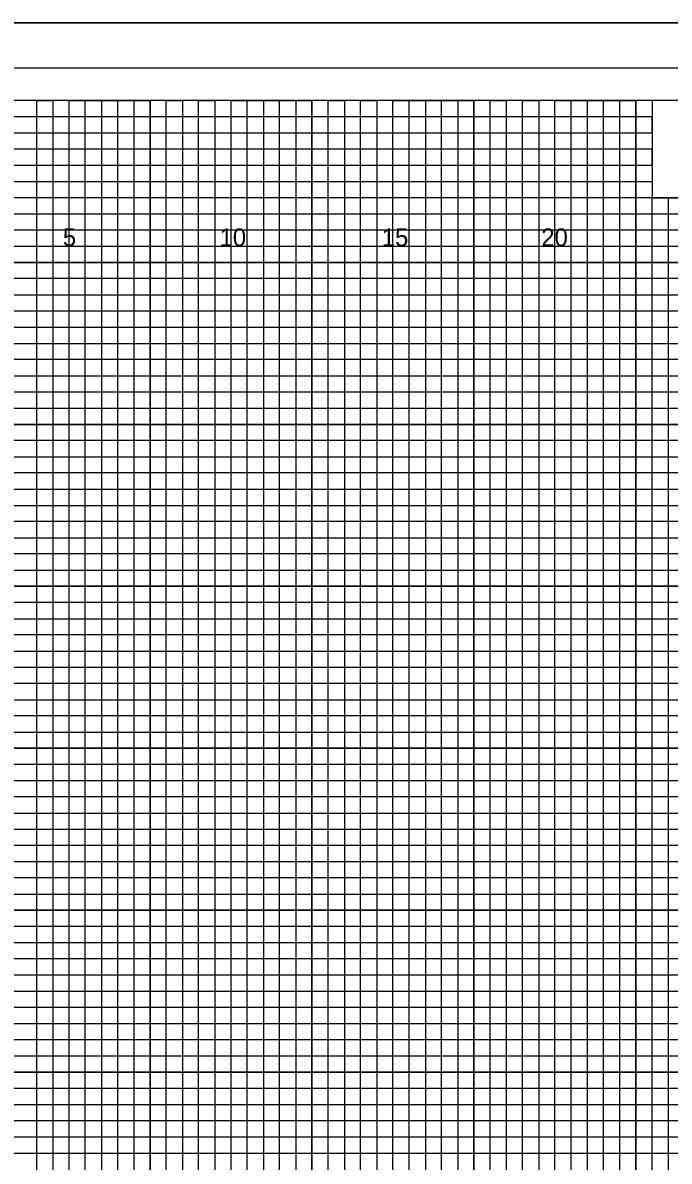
# Model space of a CAD drawing. Extents: x -4 to 103, y -2 to 351.
# Drawn here: x 54.82 to 74.78, y 32.25 to 67.4 of the extents above; entities that cross this region are included whole.
import ezdxf

# ---------------------------------------------------------------- set-up
doc = ezdxf.new("R2010")
doc.units = 0
for name, color, linetype in [('Old_Level_10', 7, 'Continuous'), ('Old_Level_16', 7, 'Continuous'), ('Old_Level_3', 7, 'Continuous'), ('Old_Level_4', 7, 'Continuous'), ('Old_Level_5', 7, 'Continuous'), ('Old_Level_6', 7, 'Continuous'), ('Old_Level_8', 7, 'Continuous'), ('Prop XS SE Text', 7, 'Continuous')]:
    doc.layers.add(name, color=color, linetype=linetype)

msp = doc.modelspace()

# ---------------------------------------------------------------- linework, layer by layer
at = {"layer": 'Old_Level_10'}
for p, q in [((56.25, 0), (56.25, 65)), ((58.75, 0), (58.75, 65)), ((61.25, 0), (61.25, 65)), ((63.75, 0), (63.75, 65)), ((66.25, 0), (66.25, 65)), ((68.75, 0), (68.75, 65)), ((71.25, 0), (71.25, 65)), ((73.75, 0), (73.75, 65)), ((0, 62.5), (74.25, 62.5)), ((0, 60), (102.5, 60)), ((0, 57.5), (102.5, 57.5)), ((0, 55), (102.5, 55)), ((0, 52.5), (102.5, 52.5)), ((0, 50), (102.5, 50)), ((0, 47.5), (102.5, 47.5)), ((0, 45), (102.5, 45)), ((0, 42.5), (102.5, 42.5)), ((0, 40), (102.5, 40)), ((0, 37.5), (102.5, 37.5)), ((0, 35), (102.5, 35)), ((0, 32.5), (102.5, 32.5))]:
    msp.add_line(p, q, dxfattribs=at)
at = {"layer": 'Old_Level_3'}
msp.add_line((-3.5, 67.4), (103.4, 67.4), dxfattribs=at)
at = {"layer": 'Old_Level_4'}
for points in [[(55.25, 0), (55.25, 65), (55.75, 65), (55.75, 0)], [(56.75, 0), (56.75, 65), (57.25, 65), (57.25, 0)], [(57.75, 0), (57.75, 65), (58.25, 65), (58.25, 0)], [(59.25, 0), (59.25, 65), (59.75, 65), (59.75, 0)], [(60.25, 0), (60.25, 65), (60.75, 65), (60.75, 0)], [(61.75, 0), (61.75, 65), (62.25, 65), (62.25, 0)], [(62.75, 0), (62.75, 65), (63.25, 65), (63.25, 0)], [(64.25, 0), (64.25, 65), (64.75, 65), (64.75, 0)], [(65.25, 0), (65.25, 65), (65.75, 65), (65.75, 0)], [(66.75, 0), (66.75, 65), (67.25, 65), (67.25, 0)], [(67.75, 0), (67.75, 65), (68.25, 65), (68.25, 0)], [(69.25, 0), (69.25, 65)], [(69.25, 65), (69.75, 65), (69.75, 0)], [(70.25, 0), (70.25, 65), (70.75, 65), (70.75, 0)], [(71.75, 0), (71.75, 65), (72.25, 65), (72.25, 0)], [(72.75, 0), (72.75, 65), (73.25, 65), (73.25, 0)], [(0, 62), (0, 63), (74.25, 63), (74.25, 63.5), (0, 63.5), (0, 64), (74.25, 64), (74.25, 64.5), (0, 64.5)], [(0, 61.5), (102.5, 61.5), (102.5, 62), (0, 62)], [(74.25, 0), (74.25, 62), (74.75, 62), (74.75, 0)], [(0, 60.5), (102.5, 60.5), (102.5, 61), (0, 61)], [(0, 59), (102.5, 59), (102.5, 59.5), (0, 59.5)], [(0, 58), (102.5, 58), (102.5, 58.5), (0, 58.5)], [(0, 56.5), (102.5, 56.5), (102.5, 57), (0, 57)], [(0, 55.5), (102.5, 55.5), (102.5, 56), (0, 56)], [(0, 54), (102.5, 54), (102.5, 54.5), (0, 54.5)], [(0, 53), (102.5, 53), (102.5, 53.5), (0, 53.5)], [(0, 51.5), (102.5, 51.5), (102.5, 52), (0, 52)], [(0, 50.5), (102.5, 50.5), (102.5, 51), (0, 51)], [(0, 49), (102.5, 49), (102.5, 49.5), (0, 49.5)], [(0, 48), (102.5, 48), (102.5, 48.5), (0, 48.5)], [(0, 46.5), (102.5, 46.5), (102.5, 47), (0, 47)], [(0, 45.5), (102.5, 45.5), (102.5, 46), (0, 46)], [(0, 44), (102.5, 44), (102.5, 44.5), (0, 44.5)], [(0, 43), (102.5, 43), (102.5, 43.5), (0, 43.5)], [(0, 41.5), (102.5, 41.5), (102.5, 42), (0, 42)], [(0, 40.5), (102.5, 40.5), (102.5, 41), (0, 41)], [(0, 39), (102.5, 39), (102.5, 39.5), (0, 39.5)], [(0, 38), (102.5, 38), (102.5, 38.5), (0, 38.5)], [(0, 36.5), (102.5, 36.5), (102.5, 37), (0, 37)], [(0, 35.5), (102.5, 35.5), (102.5, 36), (0, 36)], [(0, 34), (102.5, 34), (102.5, 34.5), (0, 34.5)], [(0, 33), (102.5, 33), (102.5, 33.5), (0, 33.5)]]:
    msp.add_lwpolyline(points, dxfattribs=at)
at = {"layer": 'Old_Level_5'}
msp.add_lwpolyline([(103.4, 67.4), (-3.5, 67.4), (-3.5, -2.425), (103.4, -2.425)], close=True, dxfattribs=at)
at = {"layer": 'Old_Level_6'}
for points in [[(102.5, 65), (0, 65), (0, 0), (102.5, 0)], [(83.75, 65), (74.25, 65), (74.25, 62), (83.75, 62)]]:
    msp.add_lwpolyline(points, close=True, dxfattribs=at)
at = {"layer": 'Old_Level_8'}
for points in [[(56.25, 0), (56.25, 65), (58.75, 65), (58.75, 0)], [(61.25, 0), (61.25, 65), (63.75, 65), (63.75, 0)], [(66.25, 0), (66.25, 65), (68.75, 65), (68.75, 0)], [(71.25, 0), (71.25, 65), (73.75, 65), (73.75, 0)], [(0, 62.5), (74.25, 62.5)], [(0, 57.5), (102.5, 57.5), (102.5, 60), (0, 60)], [(0, 52.5), (102.5, 52.5), (102.5, 55), (0, 55)], [(0, 47.5), (102.5, 47.5), (102.5, 50), (0, 50)], [(0, 42.5), (102.5, 42.5), (102.5, 45), (0, 45)], [(0, 37.5), (102.5, 37.5), (102.5, 40), (0, 40)], [(0, 32.5), (102.5, 32.5), (102.5, 35), (0, 35)]]:
    msp.add_lwpolyline(points, dxfattribs=at)
at = {"layer": 'Prop XS SE Text'}
msp.add_lwpolyline([(103, 66), (-2.8, 66), (-2.8, -1), (103, -1)], close=True, dxfattribs=at)

# ---------------------------------------------------------------- texts
at = {"layer": 'Old_Level_16'}
for s, p in [('5', (56.0574, 60.5)), ('10', (60.8971, 60.5)), ('15', (65.9057, 60.5)), ('20', (70.8312, 60.5))]:
    msp.add_text(s, height=0.55, dxfattribs=at).set_placement(p)

doc.saveas('drawing.dxf')
